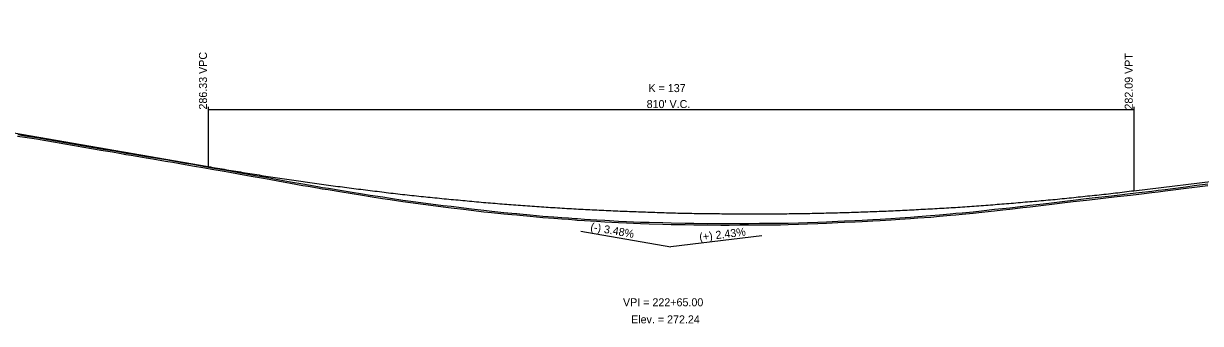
# Model space of a CAD drawing. Extents: x 1876258 to 1932803, y 754739 to 837911.
# Drawn here: x 1900062 to 1901091, y 831298 to 831561 of the extents above; entities that cross this region are included whole.
import ezdxf

# ---------------------------------------------------------------- set-up
doc = ezdxf.new("R2010")
doc.units = 0
for name, color, linetype in [('RD_DDB_GradeTX', 7, 'Continuous'), ('RD_DDB_Profile_EX', 7, 'Continuous'), ('RD_DDB_Profile_Lbl', 7, 'Continuous'), ('RD_DDB_Profile_PR', 7, 'Continuous'), ('RD_DDB_StripGrade', 7, 'Continuous'), ('RD_DDB_VCLbl', 7, 'Continuous'), ('RD_Sketch1', 7, 'Continuous')]:
    doc.layers.add(name, color=color, linetype=linetype)

msp = doc.modelspace()

# ---------------------------------------------------------------- linework, layer by layer
at = {"layer": 'RD_DDB_GradeTX'}
for p in [(1900549.3, 831379.2), (1900707.5, 831375.2)]:
    msp.add_line(p, (1900628.1, 831365.5), dxfattribs=at)
at = {"layer": 'RD_DDB_Profile_EX'}
for points in [[(1900056.3, 831462.7), (1900062.7, 831461.6), (1900072.9, 831460.1), (1900079.3, 831459), (1900089.5, 831457.2), (1900095.9, 831456.1), (1900106.1, 831454.4), (1900112.5, 831453.3), (1900122.7, 831451.5), (1900129.1, 831450.4), (1900139.3, 831448.7), (1900145.7, 831447.6), (1900151.1, 831446.6), (1900155.9, 831445.8), (1900165.6, 831444.1), (1900168.8, 831443.6), (1900174.7, 831442.6), (1900185.8, 831440.8), (1900192.2, 831439.7), (1900203, 831437.8), (1900209.4, 831436.7), (1900220.1, 831434.8), (1900226.4, 831433.7), (1900237.2, 831431.8), (1900243.7, 831430.6), (1900254.4, 831428.7), (1900260.8, 831427.6), (1900271.6, 831425.7), (1900277.9, 831424.5), (1900288.7, 831422.5), (1900295.1, 831421.4), (1900305.9, 831419.4), (1900310.7, 831418.7), (1900318.8, 831417.2), (1900323, 831416.5), (1900328.1, 831415.7), (1900340.1, 831413.7), (1900347.3, 831412.5), (1900358.1, 831410.8), (1900364.8, 831409.7), (1900375.8, 831408), (1900382.5, 831407), (1900393.4, 831405.4), (1900400.2, 831404.4), (1900411.2, 831402.9), (1900417.9, 831402), (1900428.8, 831400.7), (1900435.7, 831399.8), (1900446.6, 831398.6), (1900453.4, 831397.7), (1900464.2, 831396.4), (1900471.1, 831395.6)], [(1900471.1, 831395.6), (1900481.8, 831394.6), (1900488.7, 831393.9), (1900493.2, 831393.5), (1900495.7, 831393.2), (1900504.8, 831392.4), (1900510.3, 831391.8), (1900516, 831391.4), (1900525.5, 831390.6), (1900532.6, 831390.2), (1900538.4, 831389.7), (1900544.1, 831389.3), (1900546.1, 831389.1), (1900552.4, 831388.7), (1900563, 831388), (1900570.2, 831387.6), (1900582.1, 831387), (1900589.3, 831386.7), (1900601.4, 831386.1), (1900608.9, 831385.8), (1900621, 831385.5), (1900628.2, 831385.3), (1900640.4, 831385.1), (1900648, 831385), (1900659.8, 831384.8), (1900671.7, 831384.7), (1900679.1, 831384.7), (1900688.4, 831384.8), (1900695.9, 831384.8), (1900705.4, 831384.9), (1900711.8, 831385), (1900714.6, 831384.9), (1900723.9, 831385), (1900730.7, 831385.1), (1900739.7, 831385.4), (1900747.5, 831385.7), (1900756.7, 831386.1), (1900764.2, 831386.4), (1900774, 831386.8), (1900780, 831387.1), (1900789.1, 831387.5), (1900795.5, 831387.8), (1900804.7, 831388.3), (1900811, 831388.7), (1900820.6, 831389.3), (1900828.3, 831389.8), (1900837.7, 831390.4), (1900844.2, 831390.9), (1900855.4, 831391.7), (1900863, 831392.4), (1900872.6, 831393.3), (1900877.3, 831393.7), (1900883, 831394.1), (1900892.6, 831395.1), (1900900, 831395.9), (1900911.3, 831397.2), (1900918.5, 831398), (1900924.6, 831398.7), (1900936, 831400), (1900942.4, 831400.7), (1900953.9, 831402.1), (1900961.3, 831403), (1900972.7, 831404.4), (1900980.1, 831405.2), (1900991.7, 831406.6), (1900999.3, 831407.5), (1901011, 831408.8), (1901018.5, 831409.7), (1901030.2, 831411), (1901037.4, 831411.8), (1901048.9, 831413.2), (1901054.5, 831413.9), (1901060.6, 831414.7), (1901067.5, 831415.6), (1901078.8, 831417), (1901086.1, 831417.9), (1901097.8, 831419.4)]]:
    msp.add_lwpolyline(points, dxfattribs=at)
at = {"layer": 'RD_DDB_Profile_PR'}
for p, q in [((1901033.1, 831414.8), (1902238.1, 831561.3)), ((1900053.1, 831465.5), (1900223.1, 831435.9))]:
    msp.add_line(p, q, dxfattribs=at)
msp.add_spline([(1900223.1, 831435.9), (1900239.3, 831433.2), (1900255.5, 831430.5), (1900271.7, 831427.9), (1900287.9, 831425.4), (1900304.1, 831423), (1900320.3, 831420.8), (1900336.5, 831418.6), (1900352.7, 831416.5), (1900368.9, 831414.5), (1900385.1, 831412.5), (1900401.3, 831410.7), (1900417.5, 831409), (1900433.7, 831407.4), (1900449.9, 831405.9), (1900466.1, 831404.4), (1900482.3, 831403.1), (1900498.5, 831401.9), (1900514.7, 831400.7), (1900530.9, 831399.7), (1900547.1, 831398.7), (1900563.3, 831397.9), (1900579.5, 831397.1), (1900595.7, 831396.5), (1900611.9, 831395.9), (1900628.1, 831395.4), (1900644.3, 831395), (1900660.5, 831394.8), (1900676.7, 831394.6), (1900692.9, 831394.5), (1900709.1, 831394.5), (1900725.3, 831394.6), (1900741.5, 831394.8), (1900757.7, 831395.1), (1900773.9, 831395.5), (1900790.1, 831396), (1900806.3, 831396.6), (1900822.5, 831397.2), (1900838.7, 831398), (1900854.9, 831398.9), (1900871.1, 831399.8), (1900887.3, 831400.9), (1900903.5, 831402.1), (1900919.7, 831403.3), (1900935.9, 831404.7), (1900952.1, 831406.1), (1900968.3, 831407.6), (1900984.5, 831409.3), (1901000.7, 831411), (1901016.9, 831412.8), (1901033.1, 831414.8)], degree=3, dxfattribs=at)
at = {"layer": 'RD_DDB_VCLbl'}
for p, q in [((1900223.1, 831488.4), (1900223.1, 831435.9)), ((1900223.1, 831485.9), (1901033.1, 831485.9)), ((1901033.1, 831488.4), (1901033.1, 831414.8))]:
    msp.add_line(p, q, dxfattribs=at)
at = {"layer": 'RD_Sketch1'}
msp.add_lwpolyline([(1900056.5, 831463.9), (1900062.9, 831462.9), (1900073.1, 831461.3), (1900079.5, 831460.2), (1900089.7, 831458.4), (1900096.1, 831457.3), (1900106.3, 831455.6), (1900112.7, 831454.5), (1900122.9, 831452.7), (1900129.3, 831451.6), (1900139.5, 831449.9), (1900145.9, 831448.8), (1900151.3, 831447.8), (1900156.1, 831447), (1900165.8, 831445.3), (1900169, 831444.8), (1900174.9, 831443.8), (1900186, 831442), (1900192.4, 831440.9), (1900203.2, 831439), (1900209.6, 831438), (1900220.3, 831436.1), (1900226.7, 831434.9), (1900237.4, 831433), (1900243.9, 831431.8), (1900254.6, 831429.9), (1900261, 831428.8), (1900271.8, 831426.9), (1900278.2, 831425.7), (1900288.9, 831423.8), (1900295.3, 831422.6), (1900306.1, 831420.7), (1900310.9, 831419.9), (1900319, 831418.5), (1900323.2, 831417.7), (1900328.3, 831416.9), (1900340.3, 831414.9), (1900347.5, 831413.7), (1900358.3, 831412), (1900365, 831411), (1900376, 831409.3), (1900382.7, 831408.2), (1900393.6, 831406.6), (1900400.4, 831405.6), (1900411.4, 831404.1), (1900418.1, 831403.2), (1900428.9, 831401.9), (1900435.8, 831401.1), (1900446.7, 831399.8), (1900453.5, 831399), (1900464.4, 831397.7), (1900471.2, 831396.9), (1900481.9, 831395.8), (1900488.9, 831395.2), (1900493.3, 831394.7), (1900495.8, 831394.5), (1900504.9, 831393.6), (1900510.4, 831393.1), (1900516.1, 831392.6), (1900525.6, 831391.8), (1900532.7, 831391.4), (1900538.5, 831391), (1900544.2, 831390.5), (1900546.2, 831390.4), (1900552.4, 831389.9), (1900563.1, 831389.3), (1900570.3, 831388.9), (1900582.2, 831388.2), (1900589.3, 831387.9), (1900601.5, 831387.3), (1900609, 831387.1), (1900621, 831386.8), (1900628.2, 831386.6), (1900640.4, 831386.3), (1900648, 831386.2), (1900659.8, 831386), (1900671.7, 831386), (1900679.1, 831386), (1900688.4, 831386), (1900695.9, 831386), (1900705.4, 831386.2), (1900711.8, 831386.2), (1900714.6, 831386.2), (1900723.9, 831386.3), (1900730.7, 831386.4), (1900739.6, 831386.7), (1900747.4, 831387), (1900756.7, 831387.3), (1900764.1, 831387.6), (1900774, 831388.1), (1900780, 831388.3), (1900789, 831388.8), (1900795.4, 831389.1), (1900804.6, 831389.6), (1900811, 831389.9), (1900820.5, 831390.5), (1900828.2, 831391), (1900837.6, 831391.6), (1900844.1, 831392.2), (1900855.3, 831393), (1900862.9, 831393.6), (1900872.4, 831394.6), (1900877.2, 831395), (1900882.9, 831395.4), (1900892.5, 831396.4), (1900899.9, 831397.2), (1900911.2, 831398.5), (1900918.3, 831399.2), (1900924.5, 831399.9), (1900935.9, 831401.3), (1900942.2, 831402), (1900953.8, 831403.4), (1900961.1, 831404.2), (1900972.6, 831405.6), (1900980, 831406.5), (1900991.5, 831407.8), (1900999.2, 831408.8), (1901010.8, 831410.1), (1901018.4, 831410.9), (1901030, 831412.2), (1901037.3, 831413.1), (1901048.7, 831414.5), (1901054.4, 831415.2), (1901060.4, 831415.9), (1901067.3, 831416.8), (1901078.6, 831418.2), (1901086, 831419.2), (1901097.7, 831420.7)], dxfattribs=at)

# ---------------------------------------------------------------- texts
at = {"layer": 'RD_DDB_GradeTX'}
for s, rotation, p in [('(-) 3.48%', 350.1334, (1900557.2, 831379.9)), ('(+) 2.43%', 6.9344, (1900653.3, 831370.6))]:
    msp.add_text(s, height=7, rotation=rotation, dxfattribs=at).set_placement(p)
at = {"layer": 'RD_DDB_Profile_Lbl'}
for s, p in [('VPI = 222+65.00', (1900586.1, 831313.5)), ('Elev. = 272.24', (1900593.2, 831298.5))]:
    msp.add_text(s, height=7, dxfattribs=at).set_placement(p)
at = {"layer": 'RD_DDB_StripGrade'}
for s, p in [('286.33 VPC', (1900222.1, 831485.9)), ('282.09 VPT', (1901032.1, 831485.9))]:
    msp.add_text(s, height=7, rotation=90, dxfattribs=at).set_placement(p)
at = {"layer": 'RD_DDB_VCLbl'}
for s, p in [('K = 137', (1900608.4, 831501.2)), ("810' V.C.", (1900606.8, 831487.2))]:
    msp.add_text(s, height=7, dxfattribs=at).set_placement(p)

doc.saveas('drawing.dxf')
